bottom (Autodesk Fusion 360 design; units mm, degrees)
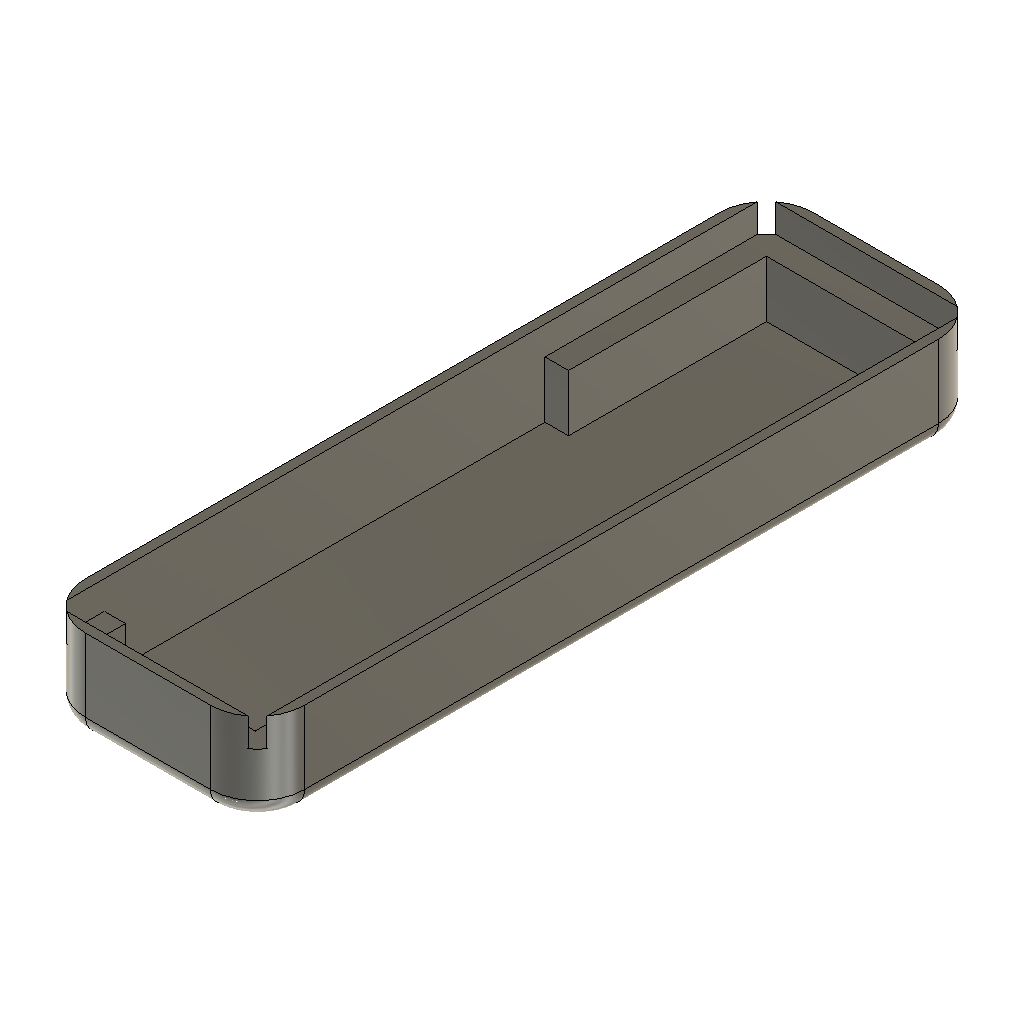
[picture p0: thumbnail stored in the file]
part number: 2026-08-16-10-17-13-464
sketch "Sketch1" plane through (0, 0, 0) normal (0, 0, 1) x axis (1, 0, 0)
  line L1 (42.5, 0) -> (0, 0)
  line L2 (42.5, -150.5) -> (42.5, 0)
  line L3 (0, -150.5) -> (42.5, -150.5)
  line L4 (0, 0) -> (0, -150.5)
  line L5 (-2, 2) -> (-2, -152.5)
  line L6 (44.5, 2) -> (-2, 2)
  line L7 (44.5, -152.5) -> (44.5, 2)
  line L8 (-2, -152.5) -> (44.5, -152.5)
  line L9 (0, -47) -> (0, 0)
  line L10 (42.5, -47) -> (42.5, 0)
  line L11 (42.5, -47) -> (0, -47)
  line L12 (0, -140.5) -> (0, -150.5)
  line L13 (42.5, -140.5) -> (42.5, -150.5)
  line L14 (0, -140.5) -> (42.5, -140.5)
  line L15 (4.5, -140.5) -> (0, -140.5)
  line L16 (38, -140.5) -> (42.5, -140.5)
  line L17 (4.5, -150.5) -> (4.5, -140.5)
  line L18 (38, -150.5) -> (38, -140.5)
  line L19 (0, -146.5) -> (42.5, -146.5)
  line L20 (42.5, -5) -> (0, -5)
  line L21 (5, -5) -> (0, -5)
  line L22 (5, -47) -> (5, -5)
  line L23 (37.5, -5) -> (42.5, -5)
  line L24 (37.5, -47) -> (37.5, -5)
  line L25 (0, -61.5) -> (0, 0)
  line L26 (0, -72.5) -> (0, -150.5)
  line L27 (-2, -61.5) -> (0, -61.5)
  line L28 (-2, -72.5) -> (0, -72.5)
  point P1 (0, 0)
  point P2 (0, 0)
  point P16 (4.5, -150.5)
  point P17 (38, -150.5)
  point P22 (5, -5)
  point P23 (5, -47)
  point P25 (37.5, -47)
  point P28 (-2, -61.5)
  point P29 (-2, -72.5)
  point P3 (42.5, 0)
  point P5 (0, -150.5)
  point P10 (0, -47)
  point P11 (42.5, -47)
  point P12 (0, -140.5)
  point P4 (42.5, -150.5)
  point P13 (42.5, -140.5)
  point P14 (4.5, -140.5)
  point P15 (38, -140.5)
  point P20 (42.5, -5)
  point P21 (0, -5)
  point P24 (37.5, -5)
  point P26 (0, -61.5)
  point P27 (0, -72.5)
  horizontal L1
  vertical L2
  horizontal L3
  vertical L4
  coincident P1 P2
  perpendicular L1 L9
  perpendicular L1 L10
  perpendicular L3 L12
  perpendicular L3 L13
  perpendicular L12 L15
  perpendicular L2 L16
  coincident L3 P16
  perpendicular L3 L17
  coincident L3 P17
  perpendicular L3 L18
  horizontal L19
  horizontal L20
  coincident L20 P22
  coincident L11 P23
  perpendicular L11 L22
  perpendicular L2 L23
  coincident L11 P25
  perpendicular L11 L24
  perpendicular L11 L25
  perpendicular L19 L26
  coincident L5 P28
  perpendicular L5 L27
  coincident L5 P29
  perpendicular L5 L28
  dimension "d1" distance P2 P3 = 42.5
  dimension "d2" distance P2 P5 = 150.5
  dimension "d3" = -2
  dimension "d4" distance P2 P10 = 47
  dimension "d5" distance P3 P11 = 47
  dimension "d6" distance P5 P12 = 10
  dimension "d7" distance P4 P13 = 10
  dimension "d8" distance P12 P14 = 4.5
  dimension "d9" distance P13 P15 = 4.5
  dimension "d10" distance L11 L19 = 99.5
  dimension "d11" distance P20 P21 = 42.5
  dimension "d12" distance P20 P24 = 5
  dimension "d19" distance P2 P26 = 61.5
  dimension "d20" distance P5 P27 = 78
extrude "Extrude1" new body sketch "Sketch1" profile of L1 L2 L3 L4 L7 L6 L5 L8 L9 L10 L12 L13 along normal blind 6
extrude "Extrude2" new body sketch "Sketch1" profile of L1 L2 L3 L4 L9 L10 L11 L12 L13 L14 L15 L16 L17 L18 L19 L20 L21 L22 L23 L24 against normal blind 12
extrude "Extrude3" add sketch "Sketch1" profile of L1 L2 L3 L4 L7 L6 L5 L8 L9 L10 L12 L13 against normal blind 12
sketch "Sketch2" plane through (0, 0, -12) normal (0, 0, -1) x axis (1, 0, 0)
  line L1 (44.5, 152.5) -> (44.5, -2)
  line L2 (-2, 152.5) -> (44.5, 152.5)
  line L3 (-2, -2) -> (-2, 152.5)
  line L4 (44.5, -2) -> (-2, -2)
  line L5 (5, 5) -> (37.5, 5)
  line L6 (5, 47) -> (5, 5)
  line L7 (0, 47) -> (5, 47)
  line L8 (0, 140.5) -> (0, 47)
  line L9 (4.5, 140.5) -> (0, 140.5)
  line L10 (4.5, 146.5) -> (4.5, 140.5)
  line L11 (38, 146.5) -> (4.5, 146.5)
  line L12 (38, 140.5) -> (38, 146.5)
  line L13 (42.5, 140.5) -> (38, 140.5)
  line L14 (42.5, 47) -> (42.5, 140.5)
  line L15 (37.5, 47) -> (42.5, 47)
  line L16 (37.5, 5) -> (37.5, 47)
  line L17 (44.5, 152.5) -> (-2, 152.5)
  line L18 (44.5, -2) -> (44.5, 152.5)
  line L19 (-2, -2) -> (44.5, -2)
  line L20 (-2, 152.5) -> (-2, -2)
  point P2 (44.5, -2)
  point P20 (44.5, -2)
  point P4 (-2, 152.5)
  point P18 (-2, 152.5)
  horizontal L17
  vertical L18
  horizontal L19
  vertical L20
  coincident P2 P20
  coincident P4 P18
extrude "Extrude4" add sketch "Sketch2" along normal blind 1.5
fillet "Fillet1" radius 10
fillet "Fillet2" radius 4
